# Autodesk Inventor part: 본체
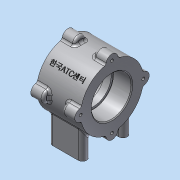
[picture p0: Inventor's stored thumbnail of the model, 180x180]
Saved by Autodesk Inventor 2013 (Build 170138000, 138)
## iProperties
Created: 2015-03
Part Number: 본체
Material: 알루미늄 6061
Document SubType Name: Modeling
Designer: dgall
Density: 2.71 g/cm^3
Mass: 450.491 g
Surface Area: 333.359 cm^2
Volume: 166.233 cm^3
Author: dgall
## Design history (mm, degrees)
sketch "스케치1"
  geometry: C1 r 37 at (0, 0); 1 further point
  constraints: 1 centre point, 1 coincident
  dimensions: "d0" = 74 diameter of C1
extrude "돌출1" new body sketch "스케치1" distance "d2" = 52; taper "d3" = 0 deg
sketch "스케치2"
  geometry: L1 (-7, 37)-(-7, 36.332); L2 (7, 37)-(7, 36.332); A1 r 37 centre (0, 0) between (0, 37) and (-7, 36.332) reference; A2 r 7 centre (0, 37) between (7, 37) and (-7, 37)
  constraints: 5 point on circle, 4 end point, 2 tangent, 1 centre point, 1 parallel, 1 vertical, 1 vertical alignment
  dimensions: "d4" = 7 radius of A2
extrude "돌출2" join sketch "스케치2" distance "d6" = 15; taper "d7" = 0 deg
fillet "모깎기1" dims "d8" = 3
fillet "모깎기2" dims "d9" = 3
fillet "모깎기3" dims "d10" = 3
fillet "모깎기4" dims "d11" = 3
sketch "스케치3"
  geometry: A1 r 37 centre (0, 0) between (-9.104, 35.863) and (9.104, 35.863) reference; A2 r 3 centre (-9.842, 38.77) between (-9.104, 35.863) and (-6.889, 38.239) reference; A3 r 7 centre (0, 37) between (6.889, 38.239) and (-6.889, 38.239) reference; A4 r 3 centre (9.842, 38.77) between (6.889, 38.239) and (9.104, 35.863) reference
extrude "돌출3" join sketch "스케치3" distance "d15" = 15; taper "d16" = 0 deg
fillet "모깎기5" dims "d17" = 3
fillet "모깎기6" dims "d18" = 3
sketch "스케치4"
  geometry: L1 (-29, 41)-(-29, 11); L2 (-19, 11)-(-19, 41); L3 (19, 41)-(19, 11); L4 (29, 11)-(29, 41); L5 (-37, 18)-(-37, 34) reference; L6 (37, 18)-(37, 34) reference; L7 (-29, 26)-(29, 26); A1 r 5 centre (-24, 11) between (-29, 11) and (-19, 11); A2 r 5 centre (-24, 41) between (-19, 41) and (-29, 41); A3 r 5 centre (24, 11) between (19, 11) and (29, 11); A4 r 5 centre (24, 41) between (29, 41) and (19, 41); 3 further points
  constraints: 10 end point, 8 point on circle, 8 tangent, 4 centre point, 4 midpoint, 3 horizontal alignment, 3 parallel, 1 equal radius, 1 vertical, 1 vertical alignment
  dimensions: "d22" = 48 distance of A3.centre A1.centre; "d24" = 10 distance between parallel lines of L1 L2; "d25" = 40 dimension on A1 A2
extrude "돌출4" join sketch "스케치4" distance "d26" = 56; taper "d27" = 0 deg
hole "구멍1" diameter "d30" = 3.459; stored, may be unused: countersink angle "d34" = 90 deg, drill point angle "d36" = 118 deg; dims "d28" = 10, "d29" = 10, "d31" = 8, "d32" = 4, "d33" = 2, "d35" = 11
node "작업 평면2"
hole "구멍2" diameter "d42" = 4.134; stored, may be unused: countersink angle "d46" = 90 deg, drill point angle "d48" = 118 deg; dims "d40" = 10, "d41" = 10, "d43" = 6, "d44" = 4, "d45" = 2, "d47" = 8
hole "구멍3" diameter "d51" = 4.134; stored, may be unused: countersink angle "d55" = 90 deg, drill point angle "d57" = 118 deg; dims "d49" = 10, "d50" = 10, "d52" = 6, "d53" = 4, "d54" = 2, "d56" = 8
hole "구멍4" diameter "d60" = 4.134; stored, may be unused: countersink angle "d64" = 90 deg, drill point angle "d66" = 118 deg; dims "d58" = 10, "d59" = 10, "d61" = 6, "d62" = 4, "d63" = 2, "d65" = 8
hole "구멍5" diameter "d69" = 4.134; stored, may be unused: countersink angle "d73" = 90 deg, drill point angle "d75" = 118 deg; dims "d67" = 10, "d68" = 10, "d70" = 6, "d71" = 4, "d72" = 2, "d74" = 8
fillet "모깎기7" dims "d76" = 3
hole "구멍6" diameter "d79" = 42; stored, may be unused: countersink angle "d83" = 90 deg, drill point angle "d85" = 0 deg; dims "d77" = 10, "d78" = 10, "d80" = 6, "d81" = 47, "d82" = 22, "d84" = 8
hole "구멍7" diameter "d88" = 47; stored, may be unused: countersink angle "d92" = 90 deg, drill point angle "d94" = 0 deg; dims "d86" = 10, "d87" = 10, "d89" = 6, "d90" = 47, "d91" = 22, "d93" = 22
fillet "모깎기8" dims "d95" = 0.3
chamfer "모따기1" distance "d96" = 1; stored, may be unused: second distance "d97" = 2, angle "d98" = 45 deg
node "작업 평면4"
  node "작업 평면3"
sketch "스케치5"
  geometry: L1 (-18.921, 0)-(18.921, 0) reference; L2 (18.921, 52)-(-18.921, 52) reference; 3 further points
  constraints: 1 midpoint, 1 vertical alignment, 1 other
  dimensions: "d100" = 26 distance from line of L2 point (0, 26)
feature "엠보싱1" sketch "스케치5" dims "d10" = 3, "d101" = 0.5, "d102" = 0
node "솔리드1"
pattern_circular "원형 패턴1" dims "d13" = 360 deg
pattern_circular "원형 패턴2" dims "d20" = 360 deg
pattern_circular "원형 패턴3" dims angle "d38" = 360 deg
mirror "대칭1"
node "작업축1"
other parameters: "d99" = 45 deg
